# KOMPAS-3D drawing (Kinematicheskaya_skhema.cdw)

Referenced files in D:\ASKON 13\Sys\: Graphic.lcs
Referenced files in D:\Учеба\4 курс\Станки\: Кинематическая схема.cdw
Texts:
  Курсовой проект
  Кинематическая схема широкоуниверсального фрезерного станка
  125 1 126 1 127 1 128 0 50 1|SPDS|125 1 126 1 127 1 128 0 50 1
  129 1 130 1 131 1 132 0 50 1|SPDS|129 1 130 1 131 1 132 0 50 1
  III
  Symbol type A
  Варианты структурных сеток
  N, кВт
  n,мин -1
  Кинематическая схема коробки скоростей после модорнизации
  Вариант 1
  (оптимальный)
  Вариант 2
  Вариант 3
  Вариант 4
  Вариант 5
  Вариант 6
  График частот вращения
  Шина, общее изображение ГОСТ 21.614-88
  Вал
  Стили документа
  Кинематическая схема
  широкоуниверсального
  фрезерного станка
  Курсовой проект-
  Давыденко П.А.
Dimensions and other numbers on the sheet: 2000; 1600; 1250; 1000; 800; 630; 500; 400; 315; 250; 1:1; 1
